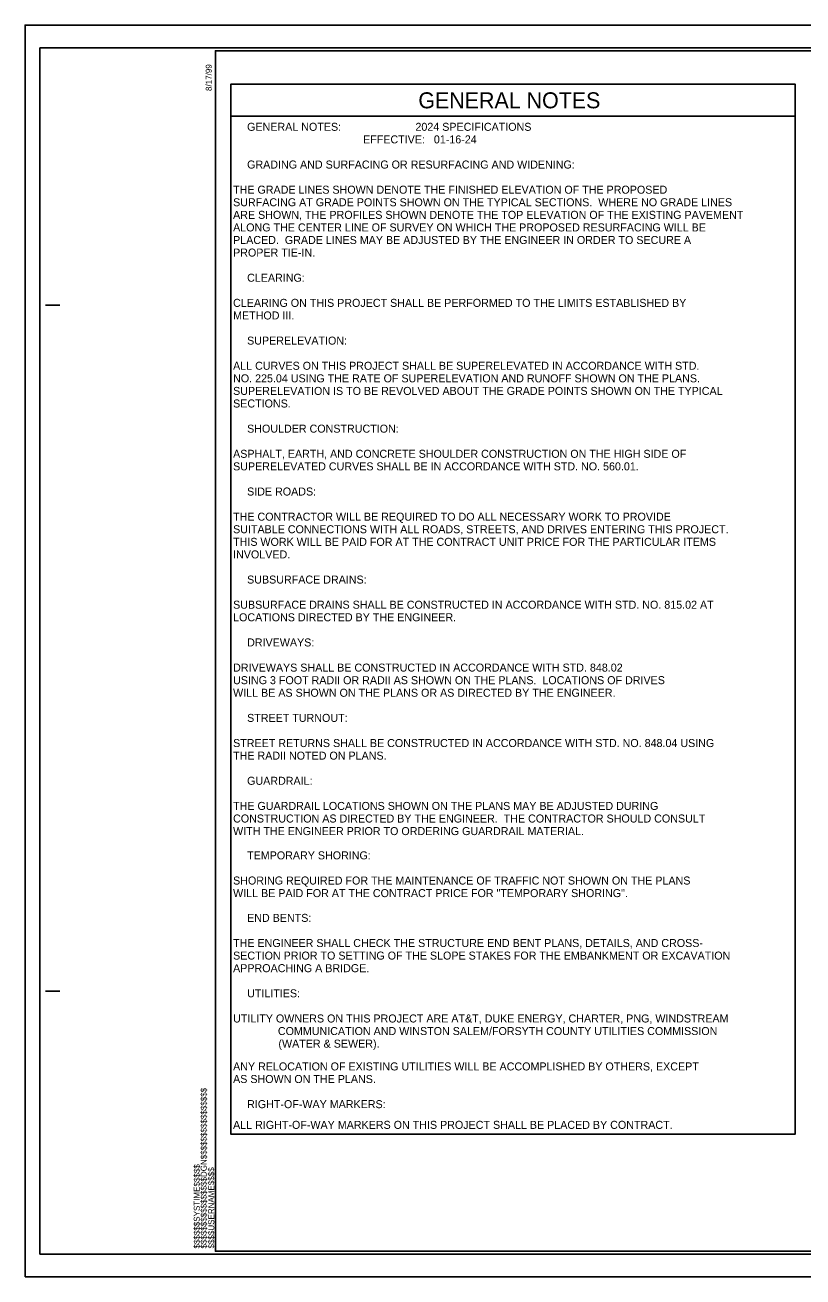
# Model space of a CAD drawing. Extents: x 93723152 to 93807327, y 70087853 to 70142603.
# Drawn here: x 93723152 to 93757166, y 70087853 to 70142603 of the extents above; entities that cross this region are included whole.
import ezdxf

# ---------------------------------------------------------------- set-up
doc = ezdxf.new("R2010")
doc.units = 0
for name, color, linetype in [('Old_Level_1', 7, 'Continuous'), ('Old_Level_40', 7, 'Continuous'), ('Sheet Cutting Line CELL', 7, 'Continuous'), ('Sheet Plan CELL', 7, 'Continuous'), ('Sheet Plot Border Inside CELL', 7, 'Continuous'), ('Sheet Plot Border Outside CELL', 7, 'Continuous')]:
    doc.layers.add(name, color=color, linetype=linetype)

msp = doc.modelspace()

# ---------------------------------------------------------------- linework, layer by layer
at = {"layer": 'Old_Level_1'}
msp.add_lwpolyline([(93732150, 70138611), (93756829, 70138611), (93756829, 70094101), (93732150, 70094101)], close=True, dxfattribs=at)
at = {"layer": 'Old_Level_40'}
msp.add_lwpolyline([(93732150, 70138611), (93756829, 70138611), (93756829, 70140011), (93732150, 70140011)], close=True, dxfattribs=at)
at = {"layer": 'Sheet Cutting Line CELL'}
for p, q in [((93807327, 70142603), (93723152, 70142603)), ((93723152, 70142603), (93723152, 70087853)), ((93723152, 70087853), (93807327, 70087853))]:
    msp.add_line(p, q, dxfattribs=at)
at = {"layer": 'Sheet Plan CELL'}
for p, q in [((93731477, 70141478), (93731477, 70141478)), ((93724052, 70130353), (93724677, 70130353)), ((93724052, 70100353), (93724677, 70100353)), ((93731477, 70088978), (93731477, 70088978))]:
    msp.add_line(p, q, dxfattribs=at)
for points in [[(93731477, 70088977), (93731476, 70141476), (93796475, 70141478), (93796476, 70133975), (93806477, 70133974), (93806477, 70088977)], [(93806477, 70141478), (93731477, 70141478), (93731477, 70088978), (93806477, 70088978)]]:
    msp.add_lwpolyline(points, close=True, dxfattribs=at)
at = {"layer": 'Sheet Plot Border Inside CELL'}
msp.add_lwpolyline([(93723802, 70088853), (93807102, 70088853), (93807102, 70141603), (93723802, 70141603)], close=True, dxfattribs=at)
at = {"layer": 'Sheet Plot Border Outside CELL'}
msp.add_lwpolyline([(93723152, 70087853), (93807327, 70087853), (93807327, 70142603), (93723152, 70142603)], close=True, dxfattribs=at)

# ---------------------------------------------------------------- texts
at = {"layer": 'Old_Level_1'}
for s, p in [('GENERAL NOTES:                         2024 SPECIFICATIONS', (93732862, 70137977)), ('                                       EFFECTIVE:   01-16-24', (93732862, 70137427)), ('GRADING AND SURFACING OR RESURFACING AND WIDENING:  ', (93732862, 70136327)), ('         THE GRADE LINES SHOWN DENOTE THE FINISHED ELEVATION OF THE PROPOSED ', (93731079, 70135227)), ('         SURFACING AT GRADE POINTS SHOWN ON THE TYPICAL SECTIONS.  WHERE NO GRADE LINES ', (93731079, 70134677)), ('         ARE SHOWN, THE PROFILES SHOWN DENOTE THE TOP ELEVATION OF THE EXISTING PAVEMENT', (93731079, 70134127)), ('         ALONG THE CENTER LINE OF SURVEY ON WHICH THE PROPOSED RESURFACING WILL BE ', (93731079, 70133577)), ('         PLACED.  GRADE LINES MAY BE ADJUSTED BY THE ENGINEER IN ORDER TO SECURE A ', (93731079, 70133027)), ('         PROPER TIE-IN. ', (93731079, 70132477)), ('CLEARING:  ', (93732862, 70131377)), ('         CLEARING ON THIS PROJECT SHALL BE PERFORMED TO THE LIMITS ESTABLISHED BY ', (93731079, 70130277)), ('         METHOD III.', (93731079, 70129727)), ('SUPERELEVATION:  ', (93732862, 70128627)), ('         ALL CURVES ON THIS PROJECT SHALL BE SUPERELEVATED IN ACCORDANCE WITH STD. ', (93731079, 70127527)), ('         NO. 225.04 USING THE RATE OF SUPERELEVATION AND RUNOFF SHOWN ON THE PLANS.', (93731079, 70126977)), ('         SUPERELEVATION IS TO BE REVOLVED ABOUT THE GRADE POINTS SHOWN ON THE TYPICAL', (93731079, 70126427)), ('         SECTIONS.  ', (93731079, 70125877)), ('SHOULDER CONSTRUCTION:  ', (93732862, 70124777)), ('         ASPHALT, EARTH, AND CONCRETE SHOULDER CONSTRUCTION ON THE HIGH SIDE OF', (93731079, 70123677)), ('         SUPERELEVATED CURVES SHALL BE IN ACCORDANCE WITH STD. NO. 560.01.', (93731079, 70123127)), ('SIDE ROADS:', (93732862, 70122027)), ('         THE CONTRACTOR WILL BE REQUIRED TO DO ALL NECESSARY WORK TO PROVIDE ', (93731079, 70120927)), ('         SUITABLE CONNECTIONS WITH ALL ROADS, STREETS, AND DRIVES ENTERING THIS PROJECT.  ', (93731079, 70120377)), ('         THIS WORK WILL BE PAID FOR AT THE CONTRACT UNIT PRICE FOR THE PARTICULAR ITEMS ', (93731079, 70119827)), ('         INVOLVED.  ', (93731079, 70119277)), ('SUBSURFACE DRAINS:', (93732862, 70118177)), ('         SUBSURFACE DRAINS SHALL BE CONSTRUCTED IN ACCORDANCE WITH STD. NO. 815.02 AT ', (93731079, 70117077)), ('         LOCATIONS DIRECTED BY THE ENGINEER.  ', (93731079, 70116527)), ('DRIVEWAYS:  ', (93732862, 70115427)), ('         DRIVEWAYS SHALL BE CONSTRUCTED IN ACCORDANCE WITH STD. 848.02', (93731079, 70114327)), ('         USING 3 FOOT RADII OR RADII AS SHOWN ON THE PLANS.  LOCATIONS OF DRIVES', (93731079, 70113777)), ('         WILL BE AS SHOWN ON THE PLANS OR AS DIRECTED BY THE ENGINEER.  ', (93731079, 70113227)), ('STREET TURNOUT:  ', (93732862, 70112127)), ('         STREET RETURNS SHALL BE CONSTRUCTED IN ACCORDANCE WITH STD. NO. 848.04 USING', (93731079, 70111027)), ('         THE RADII NOTED ON PLANS.', (93731079, 70110477)), ('GUARDRAIL:  ', (93732862, 70109377)), ('         THE GUARDRAIL LOCATIONS SHOWN ON THE PLANS MAY BE ADJUSTED DURING ', (93731079, 70108277)), ('         CONSTRUCTION AS DIRECTED BY THE ENGINEER.  THE CONTRACTOR SHOULD CONSULT', (93731079, 70107727)), ('         WITH THE ENGINEER PRIOR TO ORDERING GUARDRAIL MATERIAL.', (93731079, 70107177)), ('TEMPORARY SHORING:  ', (93732862, 70106115)), ('         SHORING REQUIRED FOR THE MAINTENANCE OF TRAFFIC NOT SHOWN ON THE PLANS ', (93731079, 70105015)), ('         WILL BE PAID FOR AT THE CONTRACT PRICE FOR "TEMPORARY SHORING".', (93731079, 70104465)), ('END BENTS:  ', (93732862, 70103382)), ('         THE ENGINEER SHALL CHECK THE STRUCTURE END BENT PLANS, DETAILS, AND CROSS-', (93731079, 70102282)), ('         SECTION PRIOR TO SETTING OF THE SLOPE STAKES FOR THE EMBANKMENT OR EXCAVATION ', (93731079, 70101732)), ('         APPROACHING A BRIDGE.  ', (93731079, 70101182)), ('UTILITIES:  ', (93732862, 70100082)), ('         UTILITY OWNERS ON THIS PROJECT ARE AT&T, DUKE ENERGY, CHARTER, PNG, WINDSTREAM', (93731079, 70098982)), ('COMMUNICATION AND WINSTON SALEM/FORSYTH COUNTY UTILITIES COMMISSION', (93734208, 70098432)), ('(WATER & SEWER).', (93734232, 70097882)), ('         ANY RELOCATION OF EXISTING UTILITIES WILL BE ACCOMPLISHED BY OTHERS, EXCEPT ', (93731079, 70096885)), ('         AS SHOWN ON THE PLANS.  ', (93731079, 70096335)), ('RIGHT-OF-WAY MARKERS:  ', (93732862, 70095235)), ('         ALL RIGHT-OF-WAY MARKERS ON THIS PROJECT SHALL BE PLACED BY CONTRACT.', (93731079, 70094330))]:
    msp.add_text(s, height=350, dxfattribs=at).set_placement(p)
at = {"layer": 'Old_Level_40'}
msp.add_text('GENERAL NOTES', height=700, dxfattribs=at).set_placement((93740349, 70138961))
at = {"layer": 'Sheet Plan CELL'}
for s, p in [('8/17/99', (93731315, 70139718)), ('$$$$$$$$$$$$$$$$DGN$$$$$$$$$$$$$$$$', (93731095, 70089096)), ('$$$$$$SYSTIME$$$$$', (93730792, 70089096)), ('$$$$USERNAME$$$$', (93731424, 70089097))]:
    msp.add_text(s, height=262.5, rotation=90, dxfattribs=at).set_placement(p)

doc.saveas('drawing.dxf')
